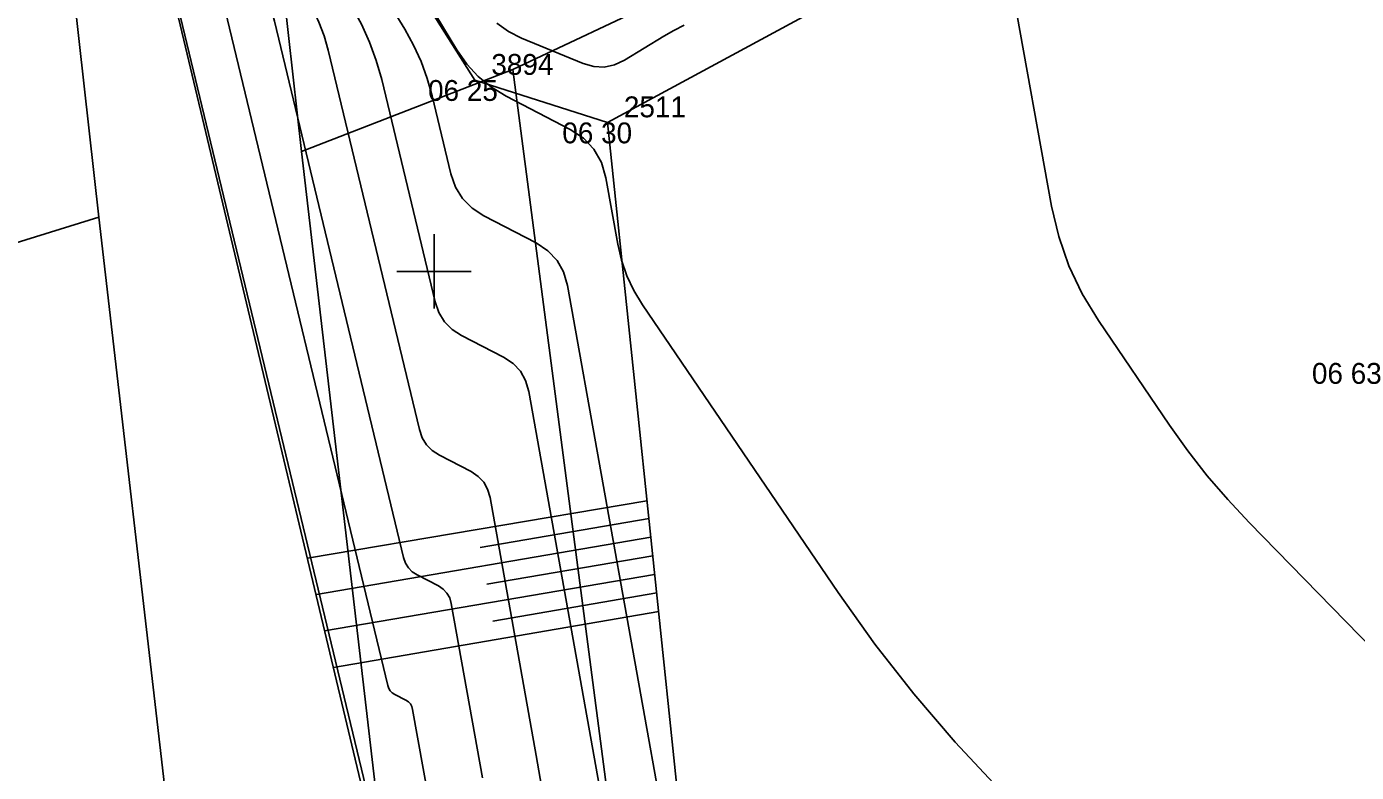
# Model space of a CAD drawing. Extents: x -703403 to -701924, y -1022520 to -1021856.
# Drawn here: x -702430.47 to -702412.61, y -1022331.73 to -1022321.71 of the extents above; entities that cross this region are included whole.
import ezdxf

# ---------------------------------------------------------------- set-up
doc = ezdxf.new("R2010")
doc.units = 0
for name, color, linetype in [('Ex_Major Contours', 7, 'Continuous'), ('Ex_Minor Contours', 7, 'Continuous'), ('Z_body', 7, 'Continuous'), ('Z_body_cisla', 7, 'Continuous'), ('Z_body_vysky_redukovane', 7, 'Continuous'), ('Z_hektometricka_sit', 7, 'Continuous'), ('Z_hrany_paty', 7, 'Continuous'), ('Z_katastr_hranice', 7, 'Continuous'), ('Z_technicke_srafy', 7, 'Continuous'), ('Z_vodni_tok', 7, 'Continuous')]:
    doc.layers.add(name, color=color, linetype=linetype)

# ---------------------------------------------------------------- blocks, each defined once
blk = doc.blocks.new('POINT_DISPLAY')
blk.add_line((0, 0), (0, 0))

msp = doc.modelspace()

# ---------------------------------------------------------------- linework, layer by layer
at = {"layer": 'Ex_Major Contours'}
for points in [[(-702426.584, -1022319.036), (-702426.539, -1022319.68), (-702426.526, -1022319.786), (-702426.5, -1022319.887), (-702426.462, -1022319.985), (-702426.412, -1022320.079), (-702425.394, -1022321.748), (-702425.275, -1022321.961), (-702425.174, -1022322.181), (-702425.09, -1022322.409), (-702425.024, -1022322.643), (-702424.773, -1022323.689), (-702424.71, -1022323.868), (-702424.616, -1022324.023), (-702424.489, -1022324.151), (-702424.33, -1022324.255), (-702423.628, -1022324.618), (-702423.471, -1022324.722), (-702423.348, -1022324.852), (-702423.26, -1022325.007), (-702423.208, -1022325.189), (-702421.852, -1022332.767)], [(-702425.071, -1022332.099), (-702425.288, -1022330.883), (-702425.299, -1022330.844), (-702425.318, -1022330.811), (-702425.344, -1022330.783), (-702425.378, -1022330.761), (-702425.527, -1022330.684), (-702425.561, -1022330.662), (-702425.588, -1022330.635), (-702425.608, -1022330.602), (-702425.621, -1022330.564), (-702427.862, -1022321.247), (-702427.88, -1022321.182), (-702427.904, -1022321.118), (-702427.932, -1022321.056), (-702427.965, -1022320.997), (-702428.156, -1022320.683), (-702428.167, -1022320.664), (-702428.175, -1022320.643), (-702428.18, -1022320.622), (-702428.183, -1022320.601), (-702428.192, -1022320.468)]]:
    msp.add_lwpolyline(points, dxfattribs=at)
at = {"layer": 'Ex_Minor Contours'}
for points in [[(-702426.986, -1022319.394), (-702426.95, -1022319.91), (-702426.939, -1022319.995), (-702426.919, -1022320.076), (-702426.888, -1022320.155), (-702426.848, -1022320.23), (-702426.105, -1022321.448), (-702425.976, -1022321.68), (-702425.866, -1022321.919), (-702425.775, -1022322.167), (-702425.703, -1022322.422), (-702424.985, -1022325.408), (-702424.935, -1022325.552), (-702424.859, -1022325.676), (-702424.757, -1022325.779), (-702424.629, -1022325.862), (-702424.066, -1022326.154), (-702423.939, -1022326.237), (-702423.84, -1022326.342), (-702423.77, -1022326.467), (-702423.728, -1022326.612), (-702422.778, -1022331.922)], [(-702427.388, -1022319.752), (-702427.361, -1022320.14), (-702427.353, -1022320.204), (-702427.337, -1022320.265), (-702427.314, -1022320.324), (-702427.284, -1022320.381), (-702426.725, -1022321.298), (-702426.628, -1022321.472), (-702426.545, -1022321.652), (-702426.477, -1022321.838), (-702426.422, -1022322.03), (-702425.197, -1022327.126), (-702425.159, -1022327.235), (-702425.102, -1022327.329), (-702425.025, -1022327.407), (-702424.928, -1022327.469), (-702424.503, -1022327.69), (-702424.407, -1022327.753), (-702424.333, -1022327.831), (-702424.28, -1022327.926), (-702424.248, -1022328.036), (-702423.628, -1022331.504), (-702423.521, -1022332.122)], [(-702417.421, -1022331.945), (-702418.003, -1022331.322), (-702418.555, -1022330.676), (-702419.079, -1022330.006), (-702419.573, -1022329.312), (-702422.2, -1022325.45), (-702422.316, -1022325.259), (-702422.41, -1022325.059), (-702422.482, -1022324.851), (-702422.533, -1022324.633), (-702422.692, -1022323.744), (-702422.752, -1022323.537), (-702422.852, -1022323.359), (-702422.992, -1022323.211), (-702423.172, -1022323.092), (-702424.03, -1022322.648), (-702424.229, -1022322.527), (-702424.406, -1022322.383), (-702424.561, -1022322.216), (-702424.694, -1022322.025), (-702426.102, -1022319.691)], [(-702424.349, -1022331.801), (-702424.768, -1022329.459), (-702424.79, -1022329.385), (-702424.826, -1022329.321), (-702424.876, -1022329.268), (-702424.94, -1022329.226), (-702425.227, -1022329.077), (-702425.293, -1022329.034), (-702425.345, -1022328.982), (-702425.383, -1022328.919), (-702425.409, -1022328.845), (-702427.142, -1022321.639), (-702427.178, -1022321.51), (-702427.224, -1022321.385), (-702427.28, -1022321.264), (-702427.345, -1022321.147), (-702427.72, -1022320.532), (-702427.741, -1022320.494), (-702427.756, -1022320.454), (-702427.766, -1022320.413), (-702427.772, -1022320.371), (-702427.79, -1022320.11)], [(-702428.594, -1022320.826), (-702428.593, -1022320.832), (-702428.593, -1022320.834), (-702428.585, -1022320.846), (-702428.583, -1022320.851), (-702428.581, -1022320.856), (-702425.833, -1022332.283)], [(-702412.011, -1022330.466), (-702414.051, -1022328.375), (-702414.34, -1022328.065), (-702414.615, -1022327.744), (-702414.876, -1022327.41), (-702415.122, -1022327.065), (-702416.077, -1022325.66), (-702416.296, -1022325.3), (-702416.473, -1022324.924), (-702416.61, -1022324.531), (-702416.706, -1022324.122), (-702417.222, -1022321.265)], [(-702421.641, -1022321.693), (-702421.778, -1022321.763), (-702421.913, -1022321.841), (-702422.444, -1022322.164), (-702422.578, -1022322.227), (-702422.715, -1022322.256), (-702422.854, -1022322.249), (-702422.996, -1022322.207), (-702423.825, -1022321.866), (-702424.001, -1022321.777), (-702424.156, -1022321.665)]]:
    msp.add_lwpolyline(points, dxfattribs=at)
at = {"layer": 'Z_hektometricka_sit'}
for p, q in [((-702425, -1022324.5), (-702425, -1022325.5)), ((-702425.5, -1022325), (-702424.5, -1022325))]:
    msp.add_line(p, q, dxfattribs=at)
at = {"layer": 'Z_hrany_paty'}
for p, q in [((-702416.11, -1022319.45), (-702422.67, -1022323)), ((-702426.16, -1022319.73), (-702424.45, -1022322.43)), ((-702424.45, -1022322.43), (-702422.67, -1022323)), ((-702422.67, -1022323), (-702421.63, -1022332.97))]:
    msp.add_line(p, q, dxfattribs=at)
at = {"layer": 'Z_katastr_hranice'}
for p, q in [((-702423.94, -1022322.29), (-702361.39, -1022292.7)), ((-702428.88, -1022304.47), (-702426.78, -1022323.39)), ((-702429.5, -1022324.27), (-702431.67, -1022304.95)), ((-702423.94, -1022322.29), (-702426.78, -1022323.39)), ((-702418.52, -1022363.82), (-702423.94, -1022322.29)), ((-702426.78, -1022323.39), (-702418.05, -1022398.57)), ((-702429.5, -1022324.27), (-702432.63, -1022325.24)), ((-702424.85, -1022364.6), (-702429.5, -1022324.27))]:
    msp.add_line(p, q, dxfattribs=at)
at = {"layer": 'Z_technicke_srafy'}
for p, q in [((-702422.14, -1022328.08), (-702426.7, -1022328.85)), ((-702422.11, -1022328.32), (-702424.38, -1022328.71)), ((-702422.09, -1022328.57), (-702426.58, -1022329.34)), ((-702422.06, -1022328.82), (-702424.29, -1022329.2)), ((-702422.04, -1022329.07), (-702426.47, -1022329.83)), ((-702422.01, -1022329.32), (-702424.21, -1022329.7)), ((-702421.98, -1022329.57), (-702426.35, -1022330.32))]:
    msp.add_line(p, q, dxfattribs=at)
at = {"layer": 'Z_vodni_tok'}
msp.add_line((-702428.61, -1022320.84), (-702425.85, -1022332.42), dxfattribs=at)

# ---------------------------------------------------------------- block references
at = {"layer": 'Z_body'}
for p in [(-702424.45, -1022322.43), (-702422.67, -1022323)]:
    msp.add_blockref('POINT_DISPLAY', p, dxfattribs=at)

# ---------------------------------------------------------------- texts
at = {"layer": 'Z_body_cisla'}
for s, p in [('3894', (-702424.23, -1022322.36)), ('2511', (-702422.45, -1022322.93))]:
    msp.add_text(s, height=0.28, dxfattribs=at).set_placement(p)
at = {"layer": 'Z_body_vysky_redukovane'}
for s, p in [('06 25', (-702425.08, -1022322.71)), ('06 30', (-702423.277, -1022323.28)), ('06 63', (-702413.21, -1022326.51))]:
    msp.add_text(s, height=0.28, dxfattribs=at).set_placement(p)

doc.saveas('drawing.dxf')
